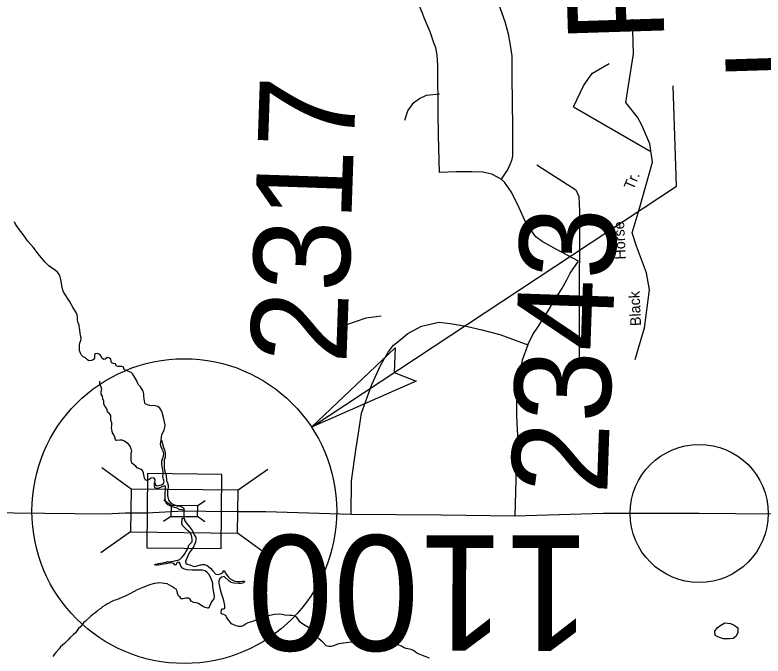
# Model space of a CAD drawing. Extents: x 2308163 to 2335412, y -96774 to 125428.
# Drawn here: x 2326219 to 2326312.3, y 122972.3 to 123052.3 of the extents above; entities that cross this region are included whole.
import ezdxf

# ---------------------------------------------------------------- set-up
doc = ezdxf.new("R2010")
doc.units = 0
for name, color, linetype in [('Default', 7, 'Continuous'), ('Old_Level_10', 7, 'Continuous'), ('Old_Level_31', 7, 'Continuous'), ('Old_Level_32', 7, 'Continuous'), ('Old_Level_35', 7, 'Continuous'), ('Old_Level_50', 7, 'Continuous'), ('Old_Level_59', 7, 'Continuous'), ('Old_Level_60', 7, 'Continuous'), ('Old_Level_8', 7, 'Continuous'), ('Sheet Data Text CELL', 7, 'Continuous'), ('Typical Terminator CELL', 7, 'Continuous')]:
    doc.layers.add(name, color=color, linetype=linetype)

# ---------------------------------------------------------------- blocks, each defined once
blk = doc.blocks.new('TERMINATOR')
at = {"layer": 'Typical Terminator CELL'}
blk.add_lwpolyline([(-0.4687, 0.0807), (0, 0), (-0.4713, -0.0833), (-0.4114, 0)], close=True, dxfattribs=at)

msp = doc.modelspace()

# ---------------------------------------------------------------- linework, layer by layer
at = {"layer": 'Default'}
for p, q in [((2326301.479, 123030.922), (2326301.086, 123043.416)), ((2326255.996, 123000.881), (2326301.479, 123030.922))]:
    msp.add_line(p, q, dxfattribs=at)
for centre, radius in [((2326240.144, 122990.411), 18.997), ((2326304.329, 122990.125), 8.606)]:
    msp.add_circle(centre, radius, dxfattribs=at)
at = {"layer": 'Old_Level_31'}
msp.add_lwpolyline([(2326244.733, 122985.736), (2326244.823, 122994.996), (2326235.555, 122995.086), (2326235.466, 122985.825), (2326244.733, 122985.736)], dxfattribs=at)
at = {"layer": 'Old_Level_32'}
for points in [[(2326271.779, 123041.739), (2326271.757, 123043.982), (2326271.748, 123044.834), (2326271.742, 123045.555), (2326271.737, 123046.074), (2326271.706, 123046.533), (2326271.662, 123047.278), (2326271.491, 123048.156), (2326271.234, 123048.785), (2326270.8, 123050.148), (2326270.05, 123051.92), (2326269.829, 123052.47), (2326269.663, 123052.84), (2326269.485, 123053.303), (2326269.439, 123053.754), (2326269.363, 123054.245), (2326269.356, 123055.384), (2326269.534, 123058.287), (2326269.538, 123058.733)], [(2326278.688, 123058.34), (2326278.56, 123057.33), (2326278.543, 123056.835), (2326278.535, 123056.387), (2326278.597, 123055.711), (2326278.67, 123055.128), (2326278.894, 123054.537), (2326279.495, 123053.077), (2326280.097, 123051.446), (2326280.493, 123049.923), (2326280.812, 123048.23), (2326280.951, 123047.11), (2326280.962, 123044.509), (2326281.033, 123038.274), (2326281.037, 123037.292)], [(2326271.955, 123032.639), (2326271.847, 123037.225), (2326271.772, 123040.141), (2326271.779, 123041.739)], [(2326281.037, 123037.292), (2326281.064, 123035.373), (2326281.051, 123034.77), (2326280.999, 123034.392), (2326280.885, 123034.001), (2326280.489, 123033.055), (2326279.635, 123031.805)], [(2326279.635, 123031.805), (2326278.469, 123032.407), (2326277.355, 123032.649), (2326276.018, 123032.707), (2326274.015, 123032.691), (2326271.955, 123032.639)], [(2326289.267, 123021.584), (2326286.612, 123023.001), (2326284.76, 123024.034), (2326283.965, 123024.622), (2326283.33, 123025.459), (2326282.606, 123026.657), (2326281.895, 123028.211), (2326280.943, 123030.181), (2326280.068, 123031.434), (2326279.635, 123031.805)], [(2326282.957, 123011.12), (2326283.565, 123012.448), (2326284.293, 123013.447), (2326284.943, 123014.546), (2326285.483, 123015.394), (2326286.292, 123016.691), (2326287.21, 123018.138), (2326287.809, 123019.239), (2326288.246, 123020.09), (2326289.267, 123021.584)], [(2326269.705, 123013.466), (2326271.865, 123013.952), (2326273.288, 123013.801), (2326275.266, 123013.478), (2326277.239, 123013.002), (2326279.49, 123012.41), (2326282.957, 123011.12)], [(2326264.588, 123008.544), (2326265.565, 123010.244), (2326266.206, 123011.088), (2326266.993, 123011.724), (2326267.991, 123012.556), (2326269.705, 123013.466)], [(2326282.957, 123011.12), (2326282.274, 123009.237), (2326281.948, 123007.563), (2326281.597, 123005.395), (2326281.569, 123003.957), (2326281.567, 123002.428), (2326281.582, 123001.382), (2326281.681, 122999.824)], [(2326260.938, 122989.987), (2326261.002, 122994.184), (2326261.521, 122997.996), (2326261.849, 123000.126), (2326262.241, 123002.61), (2326263.537, 123006.185), (2326264.588, 123008.544)], [(2326281.681, 122999.824), (2326281.557, 122997.713), (2326281.494, 122995.88), (2326281.335, 122989.793)], [(2326240.144, 122990.411), (2326235.44, 122990.153), (2326232.787, 122990.142), (2326230.334, 122990.023), (2326211.264, 122990.222), (2326203.095, 122989.994), (2326185.551, 122990.089), (2326166.763, 122990.349), (2326158.564, 122990.222), (2326136.661, 122990.068), (2326128.602, 122990.027), (2326121.262, 122989.724), (2326120.231, 122989.721), (2326117.665, 122989.676)], [(2326260.938, 122989.987), (2326250.302, 122990.306), (2326246.762, 122990.32), (2326242.827, 122990.348), (2326240.144, 122990.411)], [(2326281.335, 122989.793), (2326272.157, 122989.906), (2326260.938, 122989.987)], [(2326322.406, 122989.937), (2326304.329, 122990.125), (2326292.399, 122990.101), (2326281.335, 122989.793)]]:
    msp.add_lwpolyline(points, dxfattribs=at)
at = {"layer": 'Old_Level_35'}
for points in [[(2326296.325, 123009.322), (2326297.51, 123013.263), (2326298.12, 123018.007), (2326297.745, 123020.105), (2326296.519, 123023.423), (2326295.98, 123025.08), (2326296.827, 123028.029), (2326298.52, 123033.927), (2326298.151, 123036.174), (2326297.152, 123038.515), (2326296.626, 123039.502), (2326295.199, 123041.338), (2326295.394, 123042.672), (2326296.154, 123047.411), (2326296.005, 123051.735)], [(2326288.661, 123040.796), (2326289.898, 123043.42), (2326290.613, 123044.481), (2326291.039, 123045.009), (2326293.089, 123046.218)], [(2326267.633, 123039.147), (2326268.012, 123040.321), (2326268.735, 123041.331), (2326269.468, 123041.866), (2326270.348, 123042.244), (2326271.936, 123042.444)], [(2326288.661, 123040.796), (2326298.306, 123035.232)], [(2326284.095, 123033.571), (2326288.938, 123030.46), (2326289.32, 123029.618), (2326289.394, 123027.817), (2326289.353, 123014.827), (2326289.346, 123009.342)], [(2326260.411, 123013.674), (2326262.817, 123014.518), (2326264.676, 123014.762)]]:
    msp.add_lwpolyline(points, dxfattribs=at)
at = {"layer": 'Old_Level_50'}
for p, q in [((2326233.507, 122993.144), (2326229.845, 122995.822)), ((2326250.551, 122995.612), (2326246.835, 122993.009)), ((2326238.485, 122991.094), (2326237.569, 122991.763)), ((2326242.746, 122991.711), (2326241.817, 122991.06)), ((2326238.472, 122989.761), (2326237.543, 122989.11)), ((2326242.719, 122989.058), (2326241.803, 122989.728)), ((2326233.453, 122987.813), (2326229.738, 122985.209)), ((2326250.443, 122985), (2326246.781, 122987.678))]:
    msp.add_line(p, q, dxfattribs=at)
msp.add_lwpolyline([(2326233.453, 122987.813), (2326246.781, 122987.678), (2326246.835, 122993.009), (2326233.507, 122993.144)], close=True, dxfattribs=at)
msp.add_lwpolyline([(2326238.472, 122989.761), (2326241.803, 122989.728), (2326241.817, 122991.06), (2326238.485, 122991.094), (2326238.472, 122989.761)], dxfattribs=at)
at = {"layer": 'Old_Level_59'}
for points in [[(2326237.26, 122999.181), (2326237.288, 122999.637), (2326237.352, 122999.96), (2326237.635, 123000.519), (2326237.703, 123000.837), (2326237.745, 123001.161), (2326237.565, 123002.082), (2326237.383, 123002.687), (2326237.25, 123002.977), (2326237.071, 123003.257), (2326236.822, 123003.459), (2326236.503, 123003.521), (2326235.86, 123003.558), (2326235.533, 123003.64), (2326235.256, 123003.792), (2326235.169, 123004.105), (2326235.142, 123004.426), (2326235.096, 123004.733), (2326235.1, 123005.048), (2326235.018, 123005.36), (2326234.697, 123005.895), (2326234.473, 123006.126), (2326234.295, 123006.391), (2326234.217, 123006.663), (2326233.742, 123007.493), (2326233.499, 123007.699), (2326232.907, 123007.933), (2326232.631, 123008.07), (2326232.554, 123008.367), (2326232.368, 123008.45), (2326231.839, 123008.432), (2326231.676, 123008.489), (2326231.55, 123008.773), (2326231.307, 123008.811), (2326231.082, 123008.88), (2326230.984, 123009.346), (2326230.718, 123009.528), (2326230.519, 123009.58), (2326230.29, 123009.37), (2326230.116, 123009.315), (2326229.917, 123009.444), (2326229.77, 123009.718), (2326229.602, 123009.927), (2326229.305, 123010.039), (2326229.003, 123009.999), (2326228.952, 123009.828), (2326228.947, 123009.508), (2326228.867, 123009.292), (2326228.576, 123009.18), (2326228.26, 123009.15), (2326228.056, 123009.289), (2326227.844, 123009.51), (2326227.553, 123009.627), (2326227.346, 123009.852), (2326227.182, 123010.112), (2326227.08, 123010.415), (2326227.089, 123011.071), (2326227.13, 123011.374), (2326227.234, 123011.68), (2326227.277, 123011.999), (2326227.194, 123012.307), (2326227.14, 123012.619), (2326227.073, 123013.261), (2326227.028, 123013.435), (2326227.025, 123013.578), (2326226.893, 123013.887), (2326226.843, 123014.204), (2326226.829, 123014.545), (2326226.781, 123014.862), (2326226.653, 123015.171), (2326226.3, 123015.732), (2326225.839, 123016.601), (2326225.105, 123017.663), (2326224.996, 123017.972), (2326224.92, 123018.315), (2326224.748, 123019.291), (2326224.662, 123019.614), (2326224.534, 123019.903), (2326224.324, 123020.19), (2326224.071, 123020.407), (2326223.539, 123020.761), (2326223.258, 123020.974), (2326223.028, 123021.195), (2326222.802, 123021.442), (2326222.109, 123022.268), (2326221.292, 123023.333), (2326220.639, 123024.077), (2326220.427, 123024.359), (2326220.075, 123024.879), (2326219.482, 123025.647), (2326219.117, 123026.198), (2326218.972, 123026.472)], [(2326236.48, 122993.929), (2326236.489, 122994.339), (2326236.348, 122994.542), (2326236.023, 122994.508), (2326235.76, 122994.354), (2326235.476, 122994.242), (2326235.302, 122994.284), (2326235.196, 122994.572), (2326235.11, 122994.885), (2326235.059, 122995.187), (2326234.937, 122995.47), (2326234.757, 122995.619), (2326234.285, 122995.792), (2326234.086, 122996.033), (2326233.828, 122996.215), (2326233.617, 122996.4), (2326233.522, 122996.703), (2326233.506, 122997.013), (2326233.527, 122997.627), (2326233.585, 122997.941), (2326233.381, 122998.522), (2326233.188, 122998.757), (2326232.686, 122999.115), (2326232.402, 122999.236), (2326232.092, 122999.252), (2326231.645, 122999.222), (2326231.552, 122999.327), (2326231.48, 122999.624), (2326231.348, 122999.908), (2326231.178, 123000.178), (2326231.08, 123000.791), (2326231.123, 123001.115), (2326231.103, 123001.42), (2326230.981, 123001.699), (2326230.982, 123002.334), (2326230.798, 123002.579), (2326230.588, 123002.734), (2326230.531, 123003.046), (2326230.439, 123003.252), (2326230.226, 123003.498), (2326230.123, 123003.802), (2326230.093, 123004.118), (2326229.996, 123004.421), (2326229.929, 123004.733), (2326229.772, 123005.003), (2326229.762, 123005.308), (2326229.865, 123005.599), (2326229.768, 123005.902), (2326229.632, 123006.186), (2326229.609, 123006.599)]]:
    msp.add_lwpolyline(points, dxfattribs=at)
at = {"layer": 'Old_Level_60'}
for points in [[(2326236.48, 122993.929), (2326236.559, 122993.707), (2326236.698, 122993.56), (2326237.312, 122993.676), (2326237.563, 122993.845), (2326237.65, 122994.116), (2326237.55, 122994.41), (2326237.468, 122994.722), (2326237.525, 122995.035), (2326237.499, 122995.346), (2326237.365, 122995.981), (2326237.354, 122996.317), (2326237.359, 122996.637), (2326237.431, 122996.949), (2326237.537, 122997.255), (2326237.58, 122997.579), (2326237.52, 122997.881), (2326237.371, 122998.15), (2326237.24, 122998.434), (2326237.185, 122998.736), (2326237.218, 122999.045), (2326237.26, 122999.181)], [(2326237.26, 122999.181), (2326237.287, 122999.271), (2326237.393, 122998.973), (2326237.559, 122998.362), (2326237.672, 122998.054), (2326237.742, 122997.721), (2326237.754, 122997.411), (2326237.735, 122997.096), (2326237.64, 122996.784), (2326237.619, 122996.15), (2326237.646, 122995.814), (2326237.766, 122995.174), (2326237.888, 122994.876), (2326237.919, 122994.244), (2326238.034, 122993.941), (2326238.121, 122993.628), (2326238.114, 122993.298), (2326238.05, 122992.99), (2326238.027, 122992.676), (2326238.033, 122992.366), (2326238.171, 122991.766), (2326238.373, 122991.515), (2326238.642, 122991.338), (2326239.214, 122991.08), (2326239.518, 122991.069), (2326239.82, 122990.957), (2326240.026, 122990.828), (2326240.106, 122990.531)], [(2326240.106, 122990.531), (2326239.796, 122990.567), (2326239.544, 122990.616), (2326239.269, 122990.778), (2326238.96, 122990.845), (2326238.652, 122990.942), (2326238.366, 122991.074), (2326238.069, 122991.185), (2326237.888, 122991.415), (2326237.807, 122991.723), (2326237.753, 122992.045), (2326237.764, 122992.71), (2326237.801, 122993.014), (2326237.816, 122993.328), (2326237.779, 122993.502), (2326237.539, 122993.541), (2326237.263, 122993.393), (2326236.966, 122993.271), (2326236.661, 122993.241), (2326236.473, 122993.334), (2326236.428, 122993.63), (2326236.435, 122993.94), (2326236.457, 122993.995), (2326236.48, 122993.929)], [(2326240.123, 122989.509), (2326240.144, 122990.411), (2326240.106, 122990.531)], [(2326243.069, 122978.32), (2326243.228, 122978.396), (2326243.353, 122978.681), (2326243.503, 122978.961), (2326243.673, 122979.239), (2326243.865, 122979.487), (2326243.905, 122979.816), (2326243.721, 122980.742), (2326243.683, 122981.043), (2326243.682, 122981.378), (2326243.63, 122981.695), (2326243.372, 122982.273), (2326243.19, 122982.539), (2326242.987, 122982.779), (2326242.747, 122982.97), (2326242.427, 122983.043), (2326241.139, 122983.067), (2326240.498, 122983.109), (2326240.185, 122983.155), (2326239.906, 122983.317), (2326239.703, 122983.558), (2326239.605, 122983.851), (2326239.481, 122984.043), (2326239.232, 122983.991), (2326239.07, 122983.732), (2326238.972, 122983.655), (2326238.824, 122983.893), (2326238.5, 122983.945), (2326237.881, 122983.855), (2326237.554, 122983.78), (2326236.928, 122983.679), (2326236.619, 122983.654), (2326236.433, 122983.707), (2326236.591, 122983.787), (2326236.914, 122983.863), (2326237.861, 122984.028), (2326237.994, 122984.125), (2326238.142, 122984.09), (2326238.46, 122984.119), (2326238.765, 122984.19), (2326239.084, 122984.235), (2326239.383, 122984.306), (2326239.662, 122984.454), (2326239.891, 122984.675), (2326240.094, 122984.901), (2326240.239, 122985.156), (2326240.313, 122985.356), (2326240.51, 122985.593), (2326240.641, 122985.889), (2326240.7, 122986.151), (2326240.933, 122986.356), (2326241.107, 122986.574), (2326241.118, 122986.888), (2326241.086, 122987.204), (2326240.999, 122987.502), (2326240.844, 122987.767), (2326240.6, 122987.953), (2326240.368, 122988.169), (2326239.93, 122988.621), (2326239.853, 122988.919), (2326239.866, 122989.538), (2326240.123, 122989.509), (2326240.202, 122989.212), (2326240.39, 122988.946), (2326240.792, 122988.444), (2326241.167, 122987.944), (2326241.401, 122987.366), (2326241.579, 122987.162), (2326241.58, 122986.857), (2326241.557, 122986.543), (2326241.401, 122986.259)], [(2326241.401, 122986.259), (2326241.284, 122985.973), (2326241.124, 122985.699), (2326240.765, 122985.193), (2326240.518, 122984.628), (2326240.374, 122984.358), (2326240.285, 122984.122), (2326240.329, 122983.918), (2326240.499, 122983.78), (2326240.82, 122983.718), (2326241.116, 122983.586), (2326241.415, 122983.519), (2326242.363, 122983.746), (2326242.672, 122983.74), (2326242.974, 122983.649), (2326243.219, 122983.457), (2326243.452, 122983.241), (2326243.642, 122982.99), (2326244.061, 122982.534), (2326244.37, 122982.528), (2326244.666, 122982.61), (2326244.907, 122982.703), (2326245.08, 122982.961), (2326245.155, 122983.025), (2326245.251, 122982.716), (2326245.643, 122982.195), (2326245.854, 122981.959), (2326246.429, 122981.695), (2326246.744, 122981.639), (2326247.063, 122981.628), (2326247.372, 122981.698), (2326247.638, 122981.689), (2326247.551, 122981.458), (2326247.248, 122981.403), (2326246.93, 122981.383), (2326246.309, 122981.41), (2326246.002, 122981.517), (2326245.721, 122981.669), (2326245.109, 122982.269), (2326244.802, 122982.193), (2326244.593, 122982.043), (2326244.448, 122981.769), (2326244.438, 122981.444), (2326244.551, 122980.82), (2326244.726, 122980.174), (2326244.953, 122979.556), (2326245.044, 122979.258), (2326245.164, 122978.629), (2326245.172, 122978.314), (2326245.124, 122978.173), (2326244.812, 122978.199), (2326244.732, 122978.1), (2326244.709, 122977.786), (2326244.738, 122977.638), (2326245.047, 122977.571), (2326245.311, 122977.394)], [(2326243.069, 122978.32), (2326242.762, 122978.392), (2326242.453, 122978.514), (2326241.914, 122978.899), (2326241.606, 122978.986), (2326241.28, 122979.027), (2326241.004, 122979.169), (2326240.884, 122979.397), (2326240.65, 122979.547), (2326240.326, 122979.548), (2326240.015, 122979.467), (2326239.713, 122979.493), (2326239.624, 122979.684), (2326239.417, 122979.864), (2326239.28, 122980.143), (2326239.258, 122980.449), (2326239.114, 122980.698), (2326238.829, 122980.855), (2326238.579, 122981.031), (2326238.302, 122981.193), (2326238.022, 122981.33), (2326237.059, 122981.454), (2326236.749, 122981.44), (2326236.445, 122981.389), (2326235.813, 122981.228), (2326234.888, 122980.853), (2326234.285, 122980.59), (2326233.452, 122980.131), (2326232.851, 122979.846), (2326231.984, 122979.465), (2326231.669, 122979.349), (2326231.355, 122979.263), (2326230.865, 122979.021), (2326230.763, 122978.948), (2326230.48, 122978.815), (2326230.22, 122978.636), (2326229.952, 122978.478), (2326229.718, 122978.278), (2326229.458, 122978.099), (2326229.219, 122977.899), (2326229.004, 122977.682), (2326228.719, 122977.53), (2326228.476, 122977.325), (2326227.812, 122976.707), (2326227.593, 122976.476), (2326227.188, 122975.982), (2326226.942, 122975.762), (2326226.589, 122975.24), (2326226.328, 122975.051), (2326225.852, 122974.615), (2326225.656, 122974.358), (2326225.206, 122973.911), (2326224.722, 122973.491), (2326224.554, 122973.232), (2326224.11, 122972.78), (2326223.932, 122972.522), (2326223.735, 122972.285)], [(2326270.708, 122972.088), (2326269.833, 122972.397), (2326269.214, 122972.647), (2326268.947, 122972.819), (2326268.694, 122973.021), (2326268.41, 122973.148), (2326267.785, 122973.301), (2326267.466, 122973.429), (2326267.195, 122973.581), (2326266.29, 122973.927), (2326265.974, 122973.999), (2326265.662, 122974.045), (2326265.039, 122974.128), (2326264.71, 122974.144), (2326264.377, 122974.135), (2326264.06, 122974.075), (2326263.739, 122973.985), (2326263.441, 122973.873), (2326263.123, 122973.853), (2326262.509, 122974.007), (2326262.202, 122974.063), (2326261.897, 122974.084), (2326261.255, 122974.075), (2326260.613, 122974.042), (2326260.313, 122973.986), (2326259.356, 122973.887), (2326259.055, 122973.76), (2326258.755, 122973.598), (2326258.447, 122973.527), (2326258.137, 122973.532), (2326257.833, 122973.639), (2326257.389, 122974.066), (2326256.913, 122974.484), (2326256.694, 122974.715), (2326256.299, 122975.232), (2326255.864, 122975.694), (2326255.619, 122975.911), (2326254.778, 122976.382), (2326254.554, 122976.618), (2326254.376, 122976.879), (2326254.171, 122977.13), (2326253.901, 122977.317), (2326253.599, 122977.383), (2326253.295, 122977.414), (2326252.657, 122977.431), (2326252.352, 122977.523), (2326252.047, 122977.579), (2326251.398, 122977.51), (2326250.42, 122977.325), (2326249.815, 122977.117), (2326249.522, 122976.985), (2326248.658, 122976.664), (2326248.074, 122976.476), (2326247.788, 122976.333), (2326247.548, 122976.144), (2326247.245, 122976.017), (2326246.916, 122976.028), (2326246.594, 122976.11), (2326246.029, 122976.343), (2326245.456, 122977.12), (2326245.311, 122977.394)], [(2326309.153, 122975.289), (2326308.935, 122974.814), (2326308.566, 122974.542), (2326308.101, 122974.477), (2326307.334, 122974.478), (2326306.736, 122974.697), (2326306.327, 122974.924), (2326306.254, 122975.44), (2326306.577, 122975.861), (2326307.008, 122976.202), (2326307.531, 122976.468), (2326308.228, 122976.393), (2326308.67, 122976.19), (2326309.121, 122975.844), (2326309.153, 122975.289)]]:
    msp.add_lwpolyline(points, dxfattribs=at)

# ---------------------------------------------------------------- block references
at = {"layer": 'Default', "xscale": 30, "yscale": 30, "rotation": -146.5554162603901}
msp.add_blockref('TERMINATOR', (2326255.996, 123000.881), dxfattribs=at)

# ---------------------------------------------------------------- texts
at = {"layer": 'Old_Level_10'}
for s, rotation, p in [('Tr.', 66.88351, (2326296.101, 123030.367)), ('Horse', 92.96596, (2326295.191, 123021.803)), ('Black', 92.66996, (2326297.084, 123013.506))]:
    msp.add_text(s, height=1.3328, rotation=rotation, dxfattribs=at).set_placement(p)
at = {"layer": 'Old_Level_8'}
for s, height, rotation, p in [('2317', 11.9955, 88.02472, (2326260.338, 123008.693)), ('2343', 11.9955, 88.02472, (2326292.85, 122992.41)), ('1100', 14.3947, 179.92563, (2326290.827, 122987.377))]:
    msp.add_text(s, height=height, rotation=rotation, dxfattribs=at).set_placement(p)
at = {"layer": 'Sheet Data Text CELL'}
for s, p in [('LOCATION', (2326319.661, 123044.272)), ('PROJECT', (2326300.002, 123049.015))]:
    msp.add_text(s, height=12, rotation=91.80479, dxfattribs=at).set_placement(p)

doc.saveas('drawing.dxf')
